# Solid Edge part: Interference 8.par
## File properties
Last saved by: Lee
Revision: 59
Accuracy: 0.990
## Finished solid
Body 1: solid body, 4 faces, 4 edges, 0 vertices.
  Faces by surface: cylinder 4
  Edges by curve: intersection 4
Bounding box of the edges (mm): 101.889 x 219.073 x 304.967, from (-809.4284, 166.463, 214.5108) to (-707.5393, 385.5361, 519.4775).
Cylindrical faces by radius (mm): R91 x1, R109.5375 x1, R850 x1, R875.4 x1
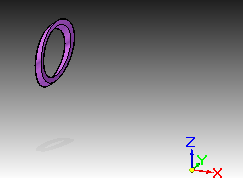
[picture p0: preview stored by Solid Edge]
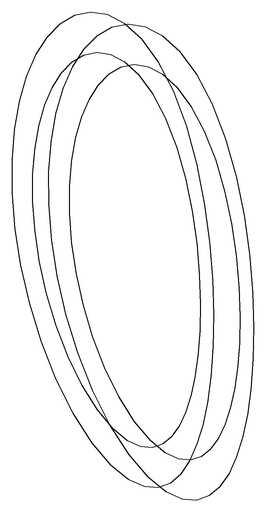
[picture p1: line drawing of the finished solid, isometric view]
